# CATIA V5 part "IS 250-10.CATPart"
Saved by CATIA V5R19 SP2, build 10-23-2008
Part number: IS 250-10
Bounding box of the stored display mesh (mm): x -18.951 to 18.951, y -18.952 to 18.952, z 0 to 70
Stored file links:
  C:\Users\Bora\Desktop\3D Katı model\IS serisi\IS 250\IS 250-10.CATPart
  C:\Program Files\Dassault Systemes\B19\intel_a\reffiles\standard\MetricThickPitch.txt
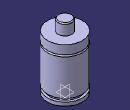
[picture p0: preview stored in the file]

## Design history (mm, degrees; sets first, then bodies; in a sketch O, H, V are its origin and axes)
Body1 (main body)
  Sketch1 on yz-plane, origin (0, 0, 0), H (0, 1, 0), V (0, 0, 1)
    point P3 (7.5, 69)
    point P5 (7.5, 69)
    point P7 (19, 48.5)
    point P8 (19, 46.5)
    point P12 (19, 46.5)
    point P13 (19, 48.5)
    line L1 (19, 0) -> (19, 4)
    line L2 (7.5, 69) -> (7.5, 58)
    arc A1 centre (6.5, 69) radius 1 from (7.5, 69) to (6.5, 70) ccw
    arc A2 centre (19, 47.5) radius 1 from (19, 48.5) to (19, 46.5) ccw
    line L3 (16.5, 7.5) -> (16.5, 4)
    line L4 (19, 7.5) -> (19, 46.5)
    line L5 (19, 48.5) -> (19, 58)
    line L6 (6.5, 70) -> (0, 70)
    point P15 (0, 70)
    line L7 (7.5, 58) -> (19, 58)
    line L8 (16.5, 7.5) -> (19, 7.5)
    line L9 (16.5, 4) -> (19, 4)
    line L10 (19, 0) -> (0, 0)
    tangency: L6 A1
    coincidence: P15 V, P3 P5, P7 P13, P8 P12
    horizontal: L7 H, L8 H, L9 H, L10 H
  Shaft1: profile Sketch1, axis Sketch1.V, angle 360
  Sketch2 on face of Shaft1 from Sketch1.L10, origin (0, 0, 0), H (1, 0, 0), V (0, -1, 0)
    point P1 (0, 0)
  Hole1: placed by Sketch2, at (0, 0, 0) direction (0, 0, 1), diameter 6.647, depth 7, threaded "M8", thread diameter 8, thread depth 7, pitch 1.25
